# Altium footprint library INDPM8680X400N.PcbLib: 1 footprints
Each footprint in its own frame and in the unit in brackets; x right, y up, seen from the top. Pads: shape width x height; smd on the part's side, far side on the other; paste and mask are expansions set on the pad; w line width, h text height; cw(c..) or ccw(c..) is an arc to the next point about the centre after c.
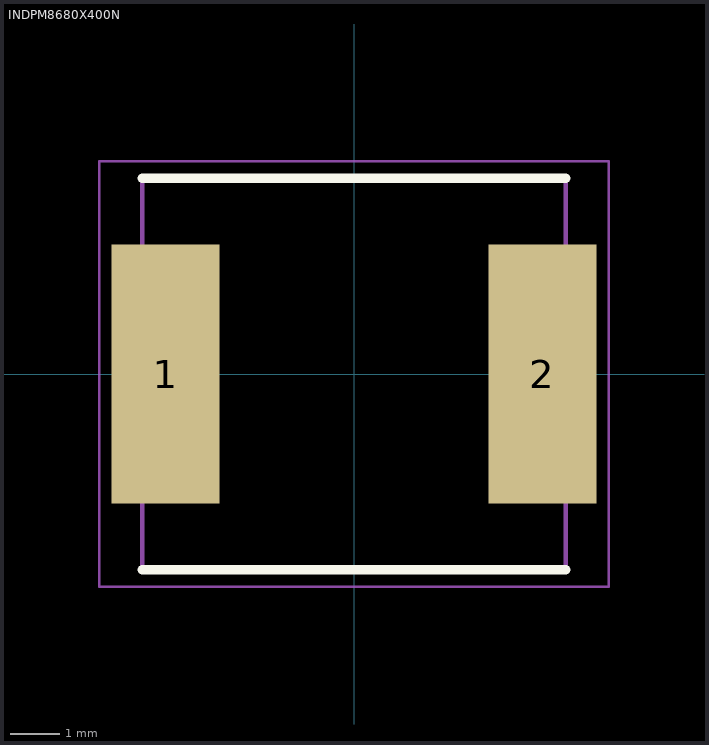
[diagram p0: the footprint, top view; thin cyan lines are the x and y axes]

## INDPM8680X400N [mm]
pads (2):
  rect 2.2x5.3 smd: 1(-3.85,0) 2(3.85,0)
Top Overlay:
  lines w0.2: -4.325,-4 4.325,-4 ; -4.325,4 4.325,4
Mechanical 15:
  lines w0.1: -4.325,-4 4.325,-4 4.325,4 -4.325,4 -4.325,-4
Mechanical 20:
  lines w0.05: -5.2,-4.35 5.2,-4.35 5.2,4.35 -5.2,4.35 -5.2,-4.35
